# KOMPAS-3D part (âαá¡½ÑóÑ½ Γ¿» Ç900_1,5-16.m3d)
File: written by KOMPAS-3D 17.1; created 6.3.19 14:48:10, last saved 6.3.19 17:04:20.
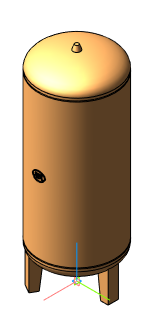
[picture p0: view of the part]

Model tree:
1. Операция без истории:1  (with: Сечение модели:1)

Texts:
  Гранлевел тип А100_1,5-16
  Гранлевел тип А150_1,5-16
  Гранлевел тип А220_1,5-16
  Гранлевел тип А350_1,5-16
  Гранлевел тип А500_1,5-16
  Гранлевел тип А700_1,5-16
  Гранлевел тип А900_1,5-16
  Гранлевел тип А1000_1,5-16
  Гранлевел тип А1400_1,5-16
  Точка начала. Х
  Точка начала. Y
  Точка начала. Z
